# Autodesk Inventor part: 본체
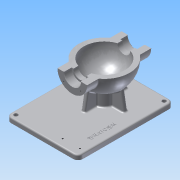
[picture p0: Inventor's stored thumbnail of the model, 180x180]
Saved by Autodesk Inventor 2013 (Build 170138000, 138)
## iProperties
Created: 2015-12
Part Number: 본체
Material: 알루미늄 6061
Document SubType Name: Modeling
Designer: mduedu
Density: 2.71 g/cm^3
Mass: 1388.36 g
Surface Area: 1121.73 cm^2
Volume: 512.309 cm^3
Author: mduedu
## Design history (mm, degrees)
sketch "스케치1"
  geometry: L1 (-53, 0)-(53, 0); A1 r 53 centre (0, 0) between (53, 0) and (-53, 0); 2 further points
  constraints: 2 coincident, 2 end point, 2 point on circle, 1 centre point, 1 horizontal, 1 midpoint
  dimensions: "d0" = 53 radius of A1
revolve "회전1" sketch "스케치1" stored, may be unused: angle "d2" = 90 deg
feature "쉘1" dims "d11" = 10
node "작업 평면1"
sketch "스케치2"
  geometry: C1 r 31 at (0, 0); 1 further point
  constraints: 1 centre point, 1 coincident
  dimensions: "d4" = 62 diameter of C1
extrude "돌출1" join sketch "스케치2" stored distance "d5" = 10; taper "d6" = 0 deg
hole "구멍1" diameter "d14" = 35; stored, may be unused: countersink angle "d18" = 90 deg, drill point angle "d20" = 0 deg; dims "d12" = 10, "d13" = 10, "d15" = 6, "d16" = 4, "d17" = 2, "d19" = 16
hole "구멍2" diameter "d23" = 27; stored, may be unused: countersink angle "d27" = 90 deg, drill point angle "d29" = 0 deg; dims "d21" = 10, "d22" = 10, "d24" = 6, "d25" = 4, "d26" = 2, "d28" = 16
fillet "모깎기1" dims "d30" = 0.3
chamfer "모따기1" distance "d40" = 1; stored, may be unused: second distance "d41" = 2, angle "d42" = 45 deg
sketch "스케치4"
  geometry: L1 (0, 0)-(0, -25); L2 (0, 0)-(-17.678, -17.678); A1 r 25 centre (0, 0) between (-17.678, -17.678) and (0, -25); 1 further point
  constraints: 4 end point, 2 point on circle, 1 centre point, 1 coincident, 1 vertical
  dimensions: "d43" = 50 diameter of A1; "d47" = 45 deg angle of L1 L2
hole "구멍4" sketch "스케치4" at (-17.678, -17.678) diameter "d49" = 3.242; stored, may be unused: countersink angle "d53" = 90 deg, drill point angle "d55" = 118 deg; dims "d50" = 11, "d51" = 4, "d52" = 2, "d54" = 13
node "작업 평면3"
sketch "스케치6" dims "d22" = 10
  geometry: L1 (-70, -75)-(130, -75); L2 (130, -75)-(130, 75); L3 (130, 75)-(-70, 75); L4 (-70, 75)-(-70, -75); 2 further points
  constraints: 8 end point, 2 parallel, 1 coincident, 1 horizontal, 1 perpendicular
  dimensions: "d158" = 200 distance of L3.end L2.end; "d159" = 150 distance of L2.end L1.end; "d162" = 75 distance from line of L1 point (0, 0); "d163" = 70 distance from line of L4 point (0, 0)
extrude "돌출3" join sketch "스케치6" distance "d80" = 10; taper "d81" = 0 deg
sketch "스케치7"
  geometry: C1 r 20 at (0, 0); 2 further points
  constraints: 2 coincident, 1 centre point
  dimensions: "d82" = 40 diameter of C1
extrude "돌출4" join sketch "스케치7" stored distance "d84" = 10; taper "d85" = 0 deg
sketch "스케치8"
  geometry: 3 further points
  constraints: 2 coincident
hole "구멍6" sketch "스케치8" at (0, 0) diameter "d86" = 20; stored, may be unused: countersink angle "d90" = 90 deg, drill point angle "d92" = 118 deg; dims "d87" = 7, "d88" = 40, "d89" = 5, "d91" = 10
fillet "모깎기2" dims "d93" = 0.3
sketch "스케치9"
  geometry: L1 (-45, -75)-(-38.245, -36.692); L2 (70, -75)-(-130, -75) reference; A1 r 53 centre (0, 0) between (42.988, 31) and (42.988, -31) reference; 1 further point
  constraints: 2 end point, 1 coincident, 1 point on circle, 1 point on line
  dimensions: "d94" = 45 horizontal distance of L1.start point (0, 0); "d160" = 80 deg angle of L2 L1
feature "리브1" sketch "스케치9" dims "d96" = 1, "d97" = 8, "d98" = 0, "d99" = 0, "d100" = 1, "d101" = 1
fillet "모깎기3" dims "d120" = 3
fillet "모깎기4" dims "d121" = 3, "d122" = 3
fillet "모깎기5" dims "d123" = 3
sketch "스케치12"
  geometry: L1 (0, 100)-(0, -100); L2 (0, 100)-(100, 100); L3 (100, 100)-(100, -100); L4 (100, -100)-(0, -100); 2 further points
  constraints: 8 end point, 3 perpendicular, 1 coincident, 1 midpoint, 1 vertical
  dimensions: "d127" = 200 distance of L2.end L3.end; "d129" = 100 distance between parallel lines of L1 L3
extrude "돌출5" cut sketch "스케치12" stored distance "d130" = 10; taper "d131" = 0 deg
fillet "모깎기10" dims "d164" = 10
fillet "모깎기11" dims "d165" = 3
sketch "스케치15"
  geometry: C1 r 4 at (-120, 65); C2 r 4 at (60, 65); C3 r 4 at (60, -65); A1 r 10 centre (-120, 65) between (-120, 75) and (-130, 65) reference; A2 r 10 centre (60, 65) between (70, 65) and (60, 75) reference; A3 r 10 centre (60, -65) between (60, -75) and (70, -65) reference; 1 further point
  constraints: 3 centre point, 3 coincident, 2 equal radius
  dimensions: "d166" = 8 diameter of C1
extrude "돌출8" cut sketch "스케치15" stored distance "d167" = 10; taper "d168" = 0 deg
sketch "스케치16"
  geometry: L1 (-130, 65)-(-130, -65) reference; L2 (-120, -75)-(60, -75) reference; 2 further points
  constraints: 1 other
  dimensions: "d169" = 70 distance from line of point (-60, -55) L1; "d170" = 20 distance from line of point (-60, -55) L2
feature "엠보싱2" sketch "스케치16" dims "d171" = 0.5, "d172" = 0
sketch "스케치17"
  geometry: L1 (-120, 75)-(60, 75) reference; L2 (-130, -65)-(-130, 65) reference; 2 further points
  constraints: 1 vertical alignment
  dimensions: "d180" = 12 distance from line of L1 point (-114, 63); "d181" = 16 distance from line of point (-114, 63) L2; "d182" = 36 distance of point (-114, 27) point (-114, 63)
hole "구멍9" sketch "스케치17" at (-114, 63), (-114, 27) diameter "d173" = 3.242; stored, may be unused: countersink angle "d177" = 90 deg, drill point angle "d179" = 0 deg; dims "d174" = 6, "d175" = 4, "d176" = 2, "d178" = 8
node "솔리드1"
mirror "대칭1"
mirror "대칭2"
pattern_circular "원형 패턴1" dims angle "d57" = 360 deg
mirror "대칭3"
pattern_circular "원형 패턴3" dims angle "d103" = 360 deg
other parameters: "d3" = 67, "d77" = -85
